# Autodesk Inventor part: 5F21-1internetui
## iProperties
Created: 2010-01
Part Number: 5F21-1internetui
Document SubType Name: Modeling
Designer: Darius
Author: Darius
Translation Standard: STEP AP203
File Name: 5F21-1.STEP
Preprocessor: SolidWorks 2003240
Postprocessor: Build: 272, Release: 10 SP3a - Date: Thu 12/15/2005
Sent Units: MILLIMETERS
Uncertainty: 1e-05
